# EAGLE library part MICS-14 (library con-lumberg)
CONNECTOR
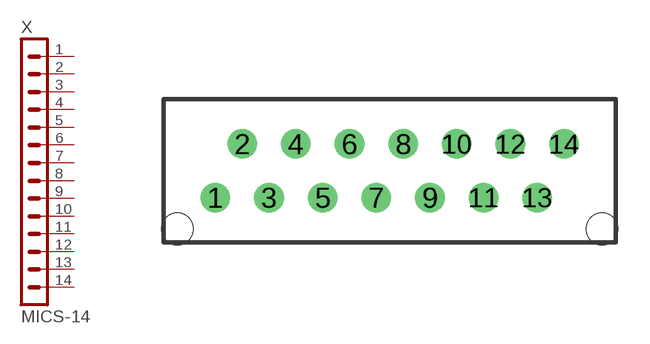
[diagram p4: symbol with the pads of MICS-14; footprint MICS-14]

Designator prefix X

## MICS-14 (OC_FARNELL: unknown; OC_NEWARK: unknown)  [MICS-14]
1  1  pas
2  2  pas
3  3  pas
4  4  pas
5  5  pas
6  6  pas
7  7  pas
8  8  pas
9  9  pas
10  10  pas
11  11  pas
12  12  pas
13  13  pas
14  14  pas

## Footprint MICS-14 (pad centres in mm)
CONNECTOR
drill 0.85 pad 1.397 round: 1 -8.255,-1.27; 2 -6.985,1.27; 3 -5.715,-1.27; 4 -4.445,1.27; 5 -3.175,-1.27; 6 -1.905,1.27; 7 -0.635,-1.27; 8 0.635,1.27; 9 1.905,-1.27; 10 3.175,1.27; 11 4.445,-1.27; 12 5.715,1.27; 13 6.985,-1.27; 14 8.255,1.27
hole 1.5 at 10.055,-2.75
hole 1.5 at -10.055,-2.75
